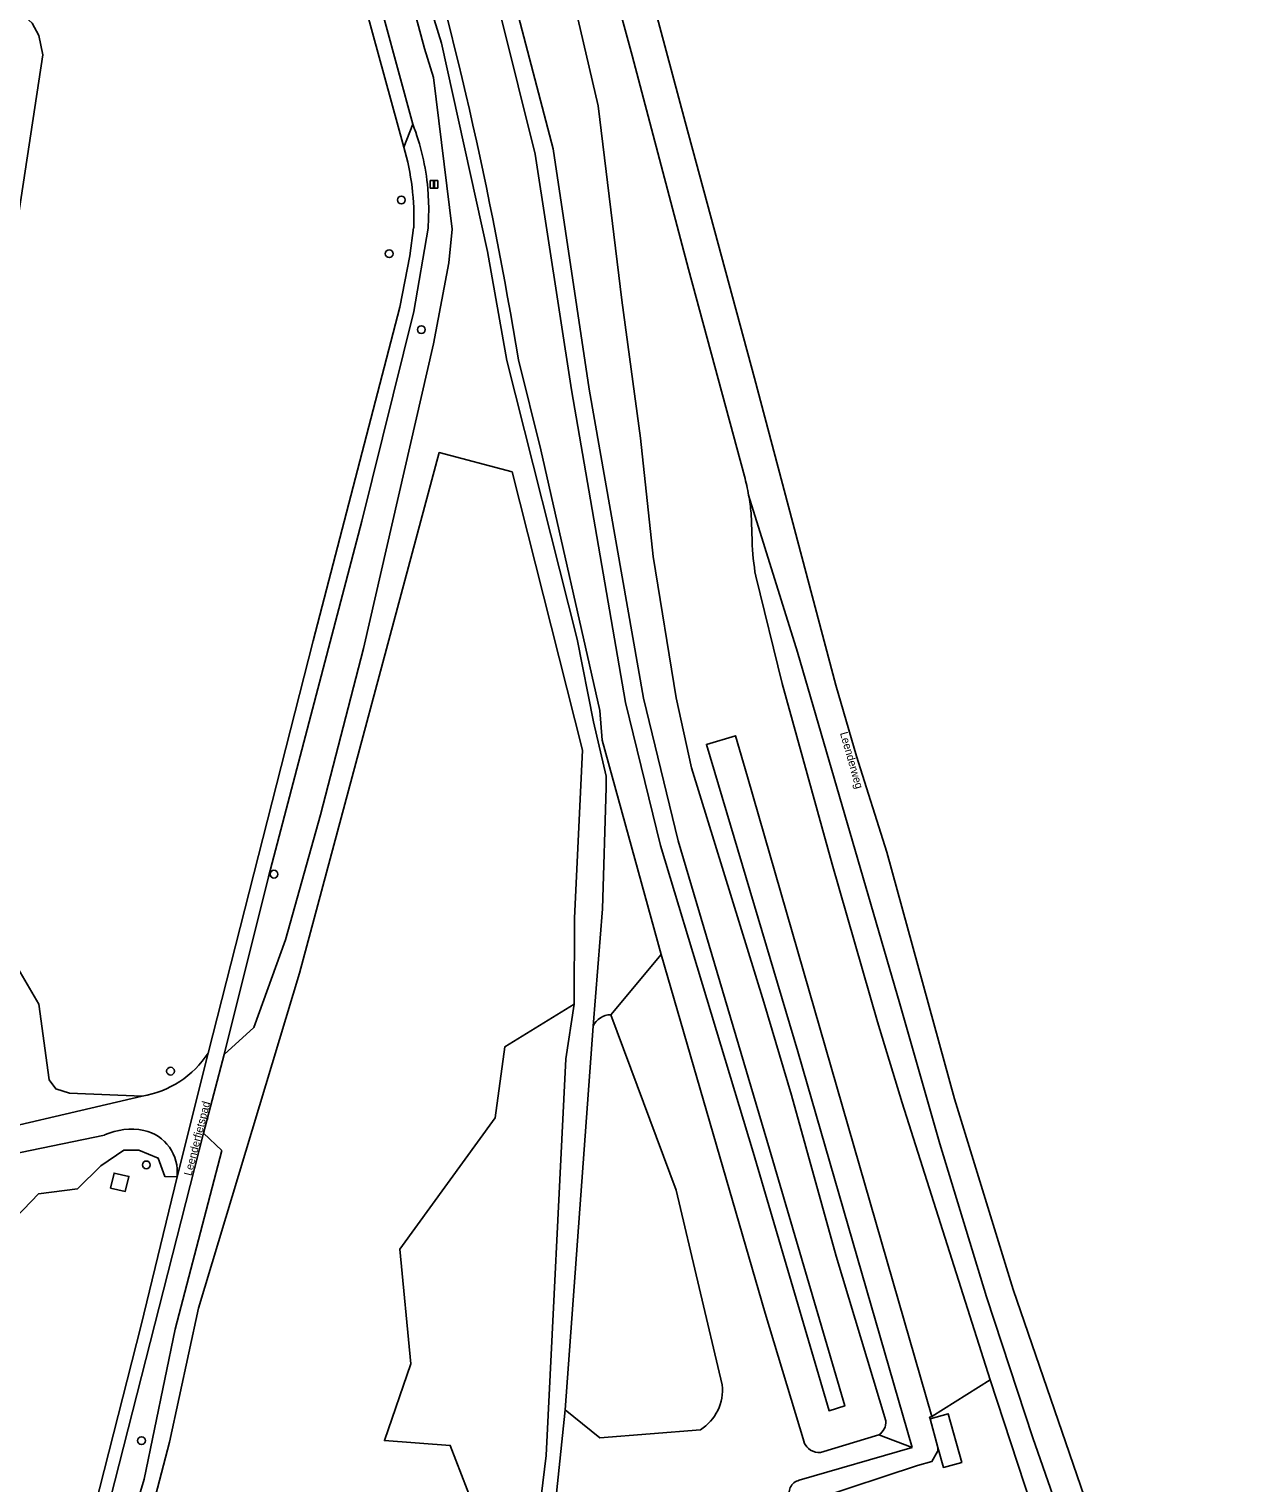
# Model space of a CAD drawing. Extents: x 162157 to 163165, y 378998 to 380775.
# Drawn here: x 162827.7 to 162981.8, y 379782.7 to 379965.5 of the extents above; entities that cross this region are included whole.
import ezdxf

# ---------------------------------------------------------------- set-up
doc = ezdxf.new("R2010")
doc.units = 0
for name, color, linetype in [('IMGEO_Afsluitpaal', 7, 'Continuous'), ('IMGEO_Berm_groen', 7, 'Continuous'), ('IMGEO_Boom', 7, 'Continuous'), ('IMGEO_Fietspad_gesloten', 7, 'Continuous'), ('IMGEO_Gemengd_bos', 7, 'Continuous'), ('IMGEO_Groenvoorziening', 7, 'Continuous'), ('IMGEO_Lage_trafo', 7, 'Continuous'), ('IMGEO_Naaldbos', 7, 'Continuous'), ('IMGEO_Openbare_ruimte_label', 7, 'Continuous'), ('IMGEO_Rijbaan_lokaal_gesloten', 7, 'Continuous'), ('IMGEO_Rijbaan_lokaal_onverhard', 7, 'Continuous'), ('IMGEO_Rijbaan_regionaal_gesloten', 7, 'Continuous'), ('IMGEO_Voetpad_onverhard', 7, 'Continuous'), ('IMGEO_Waterloop', 7, 'Continuous')]:
    doc.layers.add(name, color=color, linetype=linetype)

msp = doc.modelspace()

# ---------------------------------------------------------------- linework, layer by layer
at = {"layer": 'IMGEO_Afsluitpaal'}
for p, q in [((162878.19, 379946.51), (162878.98, 379946.51)), ((162878.98, 379946.51), (162878.19, 379946.51)), ((162878.09, 379945.61), (162878.09, 379946.41)), ((162878.09, 379946.41), (162878.09, 379945.61)), ((162878.98, 379945.51), (162878.19, 379945.51)), ((162878.19, 379945.51), (162878.98, 379945.51)), ((162879.08, 379946.41), (162879.08, 379945.61)), ((162879.08, 379945.61), (162879.08, 379946.41))]:
    msp.add_line(p, q, dxfattribs=at)
msp.add_lwpolyline([(162878.51, 379946.39), (162878.66, 379946.39), (162878.66, 379945.64), (162878.51, 379945.64), (162878.51, 379946.39)], dxfattribs=at)
for centre, start, end in [((162878.19, 379946.41), 90, 180), ((162878.19, 379946.41), 90, 180), ((162878.98, 379946.41), 0, 90), ((162878.98, 379946.41), 360, 90), ((162878.19, 379945.61), 180, 270), ((162878.19, 379945.61), 180, 270), ((162878.98, 379945.61), 270, 0), ((162878.98, 379945.61), 270, 0)]:
    msp.add_arc(centre, 0.1, start, end, dxfattribs=at)
at = {"layer": 'IMGEO_Berm_groen'}
for points in [[(162827.76, 380214.25), (162828.22, 380211.65), (162831.86, 380198.18), (162836.23, 380181.26), (162840.44, 380167.5), (162844.58, 380151.28), (162852.47, 380130.79), (162854.37, 380123.05), (162864.7, 380086.48), (162869.2, 380069.9), (162880.27, 380030.3), (162885.8, 380009.88), (162894.02, 379977.91), (162894.82, 379974.81), (162899.22, 379955.87), (162902.22, 379931.42), (162904.56, 379914.07), (162906.14, 379899.21), (162909.01, 379881.44), (162910.96, 379872.62), (162920.05, 379843.16), (162923.52, 379831.46), (162929.16, 379811.21), (162935.38, 379790.5)], [(162941.16, 379791.04), (162948.49, 379795.64)], [(162941.93, 379787.14), (162942.62, 379784.65), (162944.92, 379785.28), (162943.24, 379791.4), (162940.94, 379790.77)], [(162934.49, 379788.73), (162938.71, 379787.15)]]:
    msp.add_lwpolyline(points, dxfattribs=at)
msp.add_arc((162933.55, 379790.31), 1.83, 300.8414, 5.8723, dxfattribs=at)
at = {"layer": 'IMGEO_Boom'}
for centre in [(162874.48, 379944.04), (162872.96, 379937.28), (162876.99, 379927.74), (162858.47, 379859.25), (162845.47, 379834.48), (162842.42, 379822.69), (162841.82, 379788.01)]:
    msp.add_circle(centre, 0.489, dxfattribs=at)
at = {"layer": 'IMGEO_Fietspad_gesloten'}
for points in [[(162852.22, 379836.57), (162857.79, 379858.93), (162869.52, 379903.66), (162876.06, 379930), (162877.84, 379940.5), (162877.93, 379942.99), (162877.81, 379945.48)], [(162876.03, 379940.52), (162875.56, 379937.03), (162874.3, 379930.54), (162863.39, 379888.59), (162850.2, 379836.76)], [(162846.29, 379821.19), (162850.2, 379836.76)], [(162715.51, 379609.31), (162717.24, 379610.86), (162732.91, 379626.38), (162760.99, 379654.02), (162786.71, 379678.38), (162791.39, 379683.4), (162804.08, 379697.2), (162805.81, 379699.6), (162810.52, 379706.16), (162815.38, 379713.8), (162818.24, 379718.3), (162823.79, 379729.7), (162825.44, 379733.98), (162828.53, 379743.94), (162830.08, 379750), (162849.6, 379826.69)], [(162846.29, 379821.19), (162841.78, 379802.53), (162828.42, 379750), (162825.44, 379739.57), (162822.38, 379730.43), (162817.29, 379720.1), (162810.09, 379708.8), (162804.06, 379700.23), (162794.51, 379689.23)]]:
    msp.add_lwpolyline(points, dxfattribs=at)
for centre, radius, start, end in [((162848.07, 379942.81), 29.86, 5.1276, 21.0987), ((162843.75, 379941.78), 32.31, 357.7601, 16.0015)]:
    msp.add_arc(centre, radius, start, end, dxfattribs=at)
at = {"layer": 'IMGEO_Gemengd_bos'}
msp.add_lwpolyline([(162896.21, 379842.9), (162887.51, 379837.55), (162886.29, 379828.61), (162874.28, 379812.08), (162875.69, 379797.67), (162872.35, 379788.01), (162880.63, 379787.42), (162884.17, 379778.16), (162880.23, 379769.48), (162884.57, 379763.57), (162888.9, 379762.78)], dxfattribs=at)
at = {"layer": 'IMGEO_Groenvoorziening'}
for points in [[(162886.92, 379975.97), (162893.55, 379950.48), (162898.08, 379920.26), (162904.94, 379881.38), (162909.3, 379863.44), (162920.76, 379824.69), (162930.23, 379792.37), (162928.26, 379791.77), (162918.71, 379824.28), (162907.08, 379862.85), (162902.65, 379880.85), (162895.88, 379920.15), (162891.3, 379949.82), (162884.94, 379975.44)], [(162907.15, 379849.14), (162899.74, 379876.09), (162899.45, 379879.84), (162892.02, 379912.62), (162889.2, 379923.92)], [(162900.8, 379841.58), (162907.15, 379849.14)], [(162925.1, 379787.82), (162920.23, 379804.06), (162907.15, 379849.14)], [(162914.81, 379795.03), (162909.04, 379819.51), (162900.8, 379841.58)], [(162895.08, 379791.88), (162899.45, 379788.37), (162912.09, 379789.39)], [(162934.49, 379788.73), (162927.19, 379786.53)]]:
    msp.add_lwpolyline(points, dxfattribs=at)
for centre, radius, start, end in [((162391.87, 379842.83), 503.9, 9.2605, 16.5574), ((162900.88, 379839.05), 2.53, 91.8501, 154.1848), ((162908.91, 379794.4), 5.94, 302.4047, 6.1174), ((162926.99, 379788.55), 2.03, 201.3117, 275.7606)]:
    msp.add_arc(centre, radius, start, end, dxfattribs=at)
at = {"layer": 'IMGEO_Lage_trafo'}
msp.add_lwpolyline([(162837.92, 379819.77), (162839.78, 379819.35), (162840.23, 379821.24), (162838.38, 379821.67), (162837.92, 379819.77)], dxfattribs=at)
at = {"layer": 'IMGEO_Naaldbos'}
for points in [[(162809.65, 379831.46), (162814.86, 379840.64), (162816.5, 379843.17), (162822.02, 379847.95), (162824.4, 379848.34), (162825.99, 379847.95), (162828.9, 379842.91), (162830.23, 379833.4), (162831.04, 379832.26), (162832.76, 379831.71), (162841.89, 379831.35)], [(162846.29, 379821.19), (162844.77, 379821.22), (162843.93, 379823.55), (162841.49, 379824.55), (162839.61, 379824.55), (162836.69, 379822.59), (162833.76, 379819.66), (162828.89, 379819.07), (162826.01, 379816.09), (162818.79, 379814.79), (162816.32, 379813.06), (162811.7, 379813.01), (162805.9, 379816.58)]]:
    msp.add_lwpolyline(points, dxfattribs=at)
at = {"layer": 'IMGEO_Rijbaan_lokaal_gesloten'}
for points in [[(162805.6, 380206.95), (162811.23, 380185.22), (162832.66, 380106.4), (162836.29, 380091.77), (162838.54, 380083.95), (162839.74, 380078.68), (162841.31, 380074.11), (162845.11, 380058.55), (162849.13, 380043.85), (162853.26, 380029.71), (162857.39, 380013.63), (162859.31, 380007.93), (162861.32, 380000), (162874.8, 379950.69)], [(162875.93, 379953.56), (162863.33, 380000), (162860.3, 380010.25), (162859.82, 380012.91), (162859.06, 380014.99), (162855.7, 380027.53), (162853.05, 380036.53), (162849.58, 380050.07), (162847.39, 380056.99), (162834.02, 380108.17), (162807.15, 380207.37)], [(162875.93, 379953.56), (162874.8, 379950.69)]]:
    msp.add_lwpolyline(points, dxfattribs=at)
at = {"layer": 'IMGEO_Rijbaan_lokaal_onverhard'}
for points in [[(162852.22, 379836.57), (162855.95, 379839.98), (162859.94, 379851), (162864.32, 379866.72), (162869.74, 379887.62), (162878.52, 379925.93), (162880.46, 379936.12), (162880.89, 379940.36), (162878.53, 379959.46), (162877.4, 379963.09), (162875.48, 379970.32), (162872.22, 379980.62), (162850.44, 380055.19), (162836.52, 380107.17), (162815.65, 380183.14)], [(162820.47, 380174.33), (162830.29, 380136.99), (162838.72, 380106.17), (162845.72, 380082.59), (162848.03, 380072.7), (162850.82, 380063.54), (162873.07, 379986.28), (162876.41, 379973.93), (162879.54, 379963.77), (162885.3, 379937.58), (162887.73, 379923.86), (162896.6, 379888.82), (162898.62, 379878.42), (162900.23, 379871.56), (162900.24, 379870.17), (162899.79, 379854.89), (162898.6, 379840.15)], [(162896.21, 379842.9), (162896.24, 379853.7), (162897.24, 379874.86), (162888.41, 379909.84), (162879.25, 379912.27), (162861.7, 379846.82), (162848.98, 379804.67), (162845.36, 379787.84), (162841.08, 379771.42), (162837.43, 379759.61), (162830.64, 379733.64), (162825.27, 379718.55), (162816.1, 379702.22), (162798.13, 379679.75), (162779.64, 379660.2), (162742.85, 379624.2), (162727.43, 379610.99), (162724.91, 379609.62)], [(162888.9, 379762.78), (162891.22, 379774.13), (162892.67, 379786.15), (162895.18, 379836.01), (162896.21, 379842.9)], [(162898.6, 379840.15), (162895.08, 379791.88)], [(162849.6, 379826.69), (162852.22, 379836.57)], [(162713.85, 379607.76), (162717.44, 379608.51), (162727.49, 379614.29), (162738.34, 379623.71), (162769, 379653.1), (162785.23, 379669.17), (162801.04, 379686.58), (162809.45, 379697.28), (162816.86, 379707.88), (162824.03, 379721.72), (162828.13, 379732.54), (162830.69, 379741.74), (162836.52, 379764.13), (162842.15, 379783.15), (162846.05, 379802.03), (162851.9, 379824.51), (162849.6, 379826.69)], [(162895.08, 379791.88), (162894, 379781.4)]]:
    msp.add_lwpolyline(points, dxfattribs=at)
at = {"layer": 'IMGEO_Rijbaan_regionaal_gesloten'}
for points in [[(162848.55, 380183.16), (162855.41, 380156.79), (162869.91, 380102.56), (162884.75, 380048.07), (162892.49, 380021.3), (162903.17, 379980.05), (162910.18, 379953.87), (162918.89, 379921.63), (162929.09, 379883.04), (162931.71, 379874.1), (162935.5, 379862.01), (162944.02, 379831), (162951.41, 379807.03), (162963.67, 379771.28), (162968.32, 379757.69), (162974.41, 379738.54), (162978.16, 379724.08), (162980.3, 379709.84), (162981.67, 379700.01), (162981.78, 379690.92), (162980.19, 379681.4), (162978.93, 379672.84), (162974.17, 379658.36), (162969.49, 379647.09)], [(162917.61, 379909.32), (162910.58, 379935.34), (162903.48, 379962.19), (162894.41, 379995.63), (162889.22, 380014.47), (162884.39, 380032.32), (162875.97, 380063.72), (162870.69, 380083.46), (162863.82, 380109.08), (162860.82, 380119.94), (162857.11, 380132.94), (162856.21, 380136.12)], [(162964.7, 379647.41), (162969.09, 379655.97), (162975.55, 379672.67), (162977.11, 379680.24), (162978.44, 379692.71), (162978.22, 379702.17), (162976.88, 379710.51), (162976.51, 379717.03), (162972.97, 379732.1), (162964.45, 379758.31), (162956.72, 379780.2), (162953.88, 379788.37), (162948.02, 379806.09), (162942.16, 379825.35), (162937.14, 379842.93), (162924.28, 379887.18), (162918.14, 379906.92)], [(162918.44, 379904.64), (162918.57, 379901.17)], [(162919.04, 379896.72), (162922.37, 379883.23), (162928.63, 379860.51), (162934.33, 379840.69), (162937.43, 379830.5), (162948.49, 379795.64)], [(162948.49, 379795.64), (162954.53, 379777.27), (162963.46, 379751.56), (162967.19, 379740.36), (162969.17, 379734.12), (162970.66, 379728.45), (162972.1, 379722.52), (162974.04, 379711.48), (162974.85, 379705.48), (162975.34, 379699.72), (162975.27, 379695.23), (162974.86, 379688.18), (162974.41, 379684.19), (162972.96, 379675.16), (162972.18, 379672), (162970.88, 379667.72), (162969.5, 379664.09), (162968.62, 379664.35), (162966.37, 379658.09), (162963.82, 379651.94), (162961.92, 379647.94), (162961.74, 379647.62)]]:
    msp.add_lwpolyline(points, dxfattribs=at)
for centre, radius, start, end in [((162890.75, 379902.1), 27.81, 9.9731, 15.0288), ((162890.59, 379902.11), 27.97, 5.1919, 9.9153), ((162953.58, 379902.54), 35.04, 182.2391, 189.5714)]:
    msp.add_arc(centre, radius, start, end, dxfattribs=at)
at = {"layer": 'IMGEO_Voetpad_onverhard'}
for points in [[(162809.65, 379831.46), (162812.11, 379849.65), (162817.16, 379880.4), (162821.28, 379907.95), (162822.46, 379914.4), (162823.42, 379923.1), (162829.43, 379962.3), (162828.91, 379964.74), (162828.06, 379966.29), (162826.92, 379967.34), (162825.63, 379968.18), (162823.91, 379968.88), (162818.47, 379969.39), (162816.5, 379970.11), (162814.96, 379971.24), (162813.68, 379973.73), (162812.62, 379976.53), (162806.22, 380000), (162780.64, 380093.58), (162779.59, 380093.44)], [(162841.89, 379831.35), (162816.76, 379825.45), (162814.73, 379825.21)], [(162805.32, 379818.17), (162812.62, 379820.83), (162821.3, 379823.15), (162837.18, 379826.45)]]:
    msp.add_lwpolyline(points, dxfattribs=at)
for centre, radius, start, end in [((162839.96, 379843.41), 12.21, 279.0992, 327.0086), ((162840.58, 379818.83), 8.35, 79.277, 113.9827), ((162840.93, 379821.78), 5.39, 353.7471, 77.1275)]:
    msp.add_arc(centre, radius, start, end, dxfattribs=at)
at = {"layer": 'IMGEO_Waterloop'}
for points in [[(162938.71, 379787.15), (162924.32, 379836.94), (162912.84, 379875.57), (162916.47, 379876.66), (162918.01, 379871.51), (162941.16, 379791.04)], [(162940.94, 379790.77), (162940.89, 379790.95), (162941.16, 379791.04)], [(162940.94, 379790.77), (162941.93, 379787.14)], [(162924.49, 379783.03), (162938.71, 379787.15)], [(162948.56, 379709.49), (162948.11, 379711.52), (162947.89, 379713.23), (162945.18, 379723.32), (162942.78, 379732.23), (162938.98, 379743.78), (162926.68, 379780.68), (162939.38, 379784.87), (162941.17, 379785.41), (162941.9, 379786.65), (162941.91, 379786.83), (162941.93, 379787.14)]]:
    msp.add_lwpolyline(points, dxfattribs=at)
msp.add_arc((162924.86, 379781.43), 1.64, 102.7748, 206.594, dxfattribs=at)

# ---------------------------------------------------------------- texts
at = {"layer": 'IMGEO_Openbare_ruimte_label'}
for s, rotation, p in [('Leenderweg', 285.8982, (162929.61, 379876.99)), ('Leenderfietspad', 75.6997, (162848.09, 379821.25))]:
    msp.add_text(s, height=1, rotation=rotation, dxfattribs=at).set_placement(p)

doc.saveas('drawing.dxf')
